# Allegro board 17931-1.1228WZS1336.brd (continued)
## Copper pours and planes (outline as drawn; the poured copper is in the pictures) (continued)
3D3V_S5 on TOP: 18.16,67.29 17.94,67.51 17.94,69.34 17.35,69.93 17.35,70.59 17.53,70.77 17.94,70.77 18.88,69.83 18.88,69.04 19.03,68.89 19.97,68.89 20.07,68.78 20.07,67.44 19.92,67.29 ; 3 cut-outs
3D3V_S5 on BOTTOM: 93.78,34.57 93.73,34.62 93.73,38.41 94.19,38.86 99.62,38.86 100.08,38.41 100.08,36.63 99.6,36.15 98.76,36.15 98.63,36.27 98.63,36.83 99.27,37.47 99.27,37.72 99.09,37.9 97.03,37.9 96.83,37.69 96.83,34.67 96.73,34.57 ; 1 cut-out
3D3V_S5 on BOTTOM: 165.74,78.28 165.48,78.54 165.48,78.79 165.36,78.92 164.85,78.92 164.72,79.05 164.72,79.71 164.54,79.88 164.54,81 164.47,81.08 164.47,81.84 164.72,82.09 164.72,83.36 164.98,83.62 164.98,84.25 165.1,84.38 165.61,84.38 165.74,84.25 165.74,81.08 165.48,80.82 165.48,80.06 166.12,79.43 166.12,78.41 165.99,78.28 ; 5 cut-outs
3D3V_S5 on BOTTOM: 74.35,36.22 74.22,36.35 74.22,38.56 74.3,38.63 75.9,38.63 76.03,38.51 76.03,36.4 75.85,36.22 ; 4 cut-outs
3D3V_S5 on BOTTOM: 52.01,124.96 50.55,126.42 49.84,126.42 48.01,128.25 48.01,131.34 47.76,131.6 47.76,131.85 47.35,132.26 47.35,133.73 47.58,133.96 50.78,133.96 51.03,133.71 51.03,130.51 51.31,130.23 52.33,130.23 52.34,130.24 52.35,130.23 53.04,130.23 53.55,130.74 57.41,130.74 57.71,130.43 57.71,128.7 57.58,128.58 56.9,128.58 56.77,128.45 56.77,125.34 56.39,124.96 ; 4 cut-outs
3D3V_S5 on BOTTOM: outline of 82 points within 32.5,40.64 152.28,94.29 ; 2 cut-outs
3D3V_S5 on BOTTOM: 208.84,49.4 208.66,49.58 208.66,51.03 208.79,51.16 210.19,51.16 210.39,50.95 210.39,49.53 210.26,49.4
3D3V_S5 on L3: 56.02,107.23 60.4,102.85 60.4,93.45 58.68,91.72 55.78,91.72 55.11,92.39 55.11,95.08 54.25,95.94 54.25,101.35 49.23,106.38 49.23,112.09 48.35,112.97 48.35,114.67 44.86,118.16 42.37,118.16 41.28,117.07 40.26,117.07 40.06,117.27 40.06,117.96 41.41,119.31 41.41,125.07 42.21,125.87 42.21,129.71 39.22,132.69 35.46,132.69 34.78,133.38 34.78,134.19 34.88,134.29 35.44,134.29 35.74,133.99 50.55,133.99 51.03,133.5 51.03,126.06 50.47,125.5 50.47,120.45 52.43,118.49 52.43,117.96 53.47,116.92 54.51,116.92 56.02,115.41
3D3V_S5 on L3: 199.27,61.52 199.27,59.31 199.6,58.98 205.97,58.98 208.16,56.8 208.16,54.76 208.36,54.56 208.36,53.72 207.47,52.83 207.42,52.83 207.06,52.48 207.06,50.75 208.16,49.66 209.4,49.66 209.55,49.81 209.93,49.81 210.98,50.85 214,50.85 215.9,48.95 215.9,47.4 216.67,46.64 217.99,46.64 218.32,46.97 218.32,52.5 214,56.82 212.73,56.82 212.33,57.21 212.33,58.99 209.78,61.55 208.23,61.55 207.67,62.1 199.85,62.1
3D3V_S5 on L6: 74.81,38.91 76.33,38.91 78.36,36.88 78.39,36.88 79.05,36.22 91.82,36.22 93.68,38.08 96.27,38.08 96.29,38.05 99.7,38.05 99.98,37.77 99.98,36.83 100.76,36.04 101.48,36.04 101.62,35.9 101.62,34.99 100.28,33.66 78.79,33.66 74.55,37.9 74.55,38.66
3D3V_S5_PCH on BOTTOM: 122.46,95.15 122.41,95.2 122.41,97.44 123.04,97.44 123.88,96.6 123.88,96.04 122.99,95.15
3D3V_S5_PCH on BOTTOM: 126.54,105.26 126.5,105.3 126.5,107.37 126.62,107.49 127.13,107.49 127.43,107.19 127.92,107.19 128.03,107.3 128.46,107.3 128.53,107.24 128.53,106.83 128,106.3 128,105.87 128.2,105.67 128.2,105.41 128.04,105.26
3D3V_S5_PCH_R on BOTTOM: 128.35,98.93 128.2,99.09 128.2,101.25 128.3,101.35 129.57,101.35 129.75,101.17 129.75,100.43 129.87,100.31 130.61,100.31 130.69,100.23 130.69,99.98 130.61,99.9 130.33,99.9 130.23,100 129.62,100 129.42,99.8 129.09,99.8 128.93,99.65 128.93,99.06 128.81,98.93
3D3V_SSD on TOP: 19.79,21.29 19.74,21.34 19.74,21.49 19.43,21.79 18.6,21.79 18.44,21.95 18.44,22.86 18.55,22.96 18.75,22.96 19.94,24.16 20.2,24.16 20.27,24.08 20.27,21.39 20.17,21.29 ; 3 cut-outs
3D3V_SSD on BOTTOM: 18.47,22.43 18.01,22.89 18.01,25.81 18.15,25.95 18.66,25.95 22.1,29.39 24.91,29.39 25.83,30.32 34.56,30.32 34.58,30.34 38.44,30.34 38.62,30.51 41.63,30.51 41.84,30.31 41.84,27.89 41.76,27.81 41.24,27.81 40.71,28.35 38.64,28.35 38.36,28.06 36.65,28.06 36.45,27.87 36.45,25.91 36.35,25.81 36.35,24.46 35.54,24.46 35.54,25.88 35.46,25.96 33.91,25.96 33.86,25.91 33.86,24.46 32.03,24.46 32.03,26.21 30.53,27.71 23.45,27.71 21.71,25.97 21.71,23.15 20.98,22.43 ; 6 cut-outs
3D3V_VCCDSW on TOP: 139.56,70.59 139.41,70.74 139.41,71.17 141.42,73.18 144.5,73.18 144.78,72.9 144.78,71.5 144.68,71.4 143.36,71.4 143.31,71.35 143.31,71.1 142.8,70.59 ; 4 cut-outs
3D3V_VCCDSW on BOTTOM: 155.1,96.7 155.1,97.82 155.6,98.32 155.98,98.32 156.06,98.25 156.06,97.74 155.83,97.51 155.83,96.7
3D3V_VCCPRIM on TOP: 107.78,91.98 107.64,91.85 107.11,91.85 107.04,91.92 107.04,92.41 106.94,92.51 104.14,92.51 104.09,92.46 103.66,92.46 103.42,92.7 101.19,92.7 101.07,92.81 101.07,93.23 101.22,93.38 101.31,93.38 101.7,93.77 101.7,94.11 101.83,94.24 104.37,94.24 104.98,93.63 105.46,93.63 105.67,93.83 107.52,93.83 107.78,93.57 ; 4 cut-outs
3D3V_VCCPRIM on TOP: 111.64,88.29 111.42,88.51 111.42,89.14 111.55,89.28 113.64,89.28 113.95,89.59 114.96,89.59 115.01,89.54 115.01,88.88 114.91,88.77 114.71,88.77 114.23,88.29 ; 1 cut-out
3D3V_VCCPRIM on BOTTOM: 106.2,92.51 106.02,92.69 106.02,93.73 106.05,93.75 107.8,93.75 108.13,93.42 108.13,92.66 107.98,92.51
3D3V_VCCPRIM on BOTTOM: 122.38,89 122.02,89.36 122.02,89.69 122.2,89.87 126.62,89.87 126.75,89.74 126.75,89.16 126.6,89
3D3V_VCCPRIM on L3: 102.37,93.47 105.39,93.47 105.64,93.72 105.64,96.72 105.8,96.88 106.03,96.88 106.23,96.68 106.23,94.72 106.41,94.53 112.37,94.53 113.62,93.29 113.62,91.97 113.92,91.67 114.73,91.67 114.79,91.62 115.95,91.62 116.84,92.51 122.43,92.51 122.81,92.13 122.81,89.69 122.46,89.33 122.13,89.33 122.05,89.41 122.05,90.1 121.85,90.3 121.49,90.3 121.16,89.97 115.94,89.97 114.56,88.58 113.99,88.58 112.09,90.48 111.89,90.48 110.38,91.98 106.35,91.98 106.23,92.1 106.23,92.4 105.99,92.64 101.3,92.64 101.04,92.9 101.04,93.44 101.2,93.6 101.6,93.6 101.7,93.7 101.7,94.08 101.86,94.24 102.11,94.24 102.29,94.06 102.29,93.55
3D3V_VCCPRTC on TOP: 164.6,66.78 164.49,66.88 164.49,67.21 165.2,67.92 167.24,67.92 167.31,67.84 167.31,66.96 167.14,66.78 ; 1 cut-out
3D3V_VCCPRTC on L5: 112.83,94.62 114.94,94.62 115.22,94.9 117.1,94.9 117.73,94.26 117.73,93.45 117.4,93.12 116.87,93.12 116.79,93.19 116.79,93.96 116.59,94.16 116.36,94.16 116.09,93.89 116.09,93.59 115.52,93.02 112.86,93.02 112.4,93.47 112.4,94.18
3D3V_WLAN on TOP: 29.52,101.35 29.24,101.63 29.24,101.68 28.96,101.96 28.96,103.51 29.24,103.79 29.24,104.9 29.52,105.18 32.16,105.18 32.21,105.13 32.21,101.68 31.88,101.35 ; 4 cut-outs
3D3V_WLAN on TOP: 56.98,93.55 56.47,94.06 56.47,98.5 55.17,99.8 55.17,103.4 53.93,104.65 52.28,104.65 51.84,105.08 49.28,105.08 48.77,104.57 45.47,104.57 45.34,104.7 45.34,104.83 45.22,104.95 43.18,104.95 43.06,105.08 43.06,105.46 42.75,105.77 42.75,106.27 42.88,106.4 43.34,106.4 44.02,105.72 44.5,105.72 44.94,106.15 44.94,106.78 45.8,107.65 47.53,107.65 47.78,107.39 49.46,107.39 49.61,107.24 50.7,107.24 50.98,107.52 54.36,107.52 60.4,101.47 60.4,95.07 58.88,93.55 ; 3 cut-outs
3D3V_WLAN on BOTTOM: 57.18,93.65 57.05,93.78 57.05,95.84 57.28,96.06 58.17,96.06 58.3,95.94 58.3,95.05 58.42,94.92 58.55,94.92 58.8,94.67 58.8,94.29 58.17,93.65
3D3V_WLAN on BOTTOM: 31.02,101.96 29.31,103.66 29.31,109.78 29.82,110.29 38.05,110.29 39.12,111.35 42.14,111.35 43.21,110.29 47.65,110.29 47.93,110.01 47.93,109.73 47.91,109.7 47.91,108.87 48.49,108.28 48.87,108.28 49.79,107.37 49.79,104.52 49.58,104.32 48.64,104.32 48.52,104.45 48.52,105.92 48.44,106 47.63,106 47.5,106.12 47.5,106.55 47.3,106.76 46.84,106.76 46.37,106.83 46.04,106.48 41.91,106.48 41.56,106.12 35.44,106.12 35.08,106.48 32.52,106.48 31.85,105.82 31.85,102.11 31.7,101.96
+DC_IN on TOP: 24.62,123.45 24.36,123.7 24.36,130.02 24.44,130.1 26.04,130.1 26.17,130.23 26.93,130.23 28.07,131.37 29.59,131.37 29.85,131.12 29.85,129.72 29.47,129.34 28.71,129.34 28.58,129.21 28.58,128.96 28.51,128.89 26.41,128.89 26.29,128.78 26.29,127.79 26.17,127.66 25.76,127.66 25.66,127.56 25.66,126.57 25.94,126.29 26.55,126.29 26.72,126.11 26.72,125.48 26.2,124.96 26.2,124.63 25.96,124.39 25.96,123.8 25.61,123.45 ; 7 cut-outs
+DC_IN_C on TOP: 20.78,120.45 20.58,120.65 20.58,124.92 20.37,125.12 17.58,125.12 17.35,125.35 17.35,127.38 17.4,127.43 18.42,127.43 19.41,126.44 20.67,126.44 20.77,126.54 20.77,129.38 20.75,129.39 20.75,129.87 20.98,130.1 23.83,130.1 24.21,129.72 24.21,120.65 24.01,120.45 ; 4 cut-outs
+DC_IN_C on BOTTOM: 21.96,124.14 21.8,124.31 21.8,128.04 22.02,128.27 24.16,128.27 24.95,127.48 24.95,124.68 24.41,124.14
+SDC_IN on TOP: 34.93,123.5 34.8,123.62 34.8,124.13 34.55,124.39 33.15,124.39 33.02,124.51 33.02,125.02 32.9,125.15 31.91,125.15 31.8,125.25 31.8,125.63 31.63,125.81 31.19,125.81 30.86,125.48 30.86,124 30.74,123.88 30.1,123.88 29.98,124 29.98,126.85 30.43,127.31 31.04,127.31 31.22,127.13 31.22,126.65 31.58,126.29 32.62,126.29 33.15,126.82 33.48,126.82 33.63,126.98 33.63,127.53 33.18,127.99 33.18,128.6 33.28,128.7 35.26,128.7 35.39,128.58 35.39,127.48 35.44,127.43 35.44,125.78 35.82,125.4 35.82,123.75 35.56,123.5 ; 8 cut-outs
+SDC_IN on TOP: 203.03,52.55 202.82,52.76 202.82,53.75 203.89,54.81 204.3,54.81 204.37,54.74 204.37,53.52 204.27,53.42 203.86,53.42 203.63,53.19 203.63,52.63 203.56,52.55 ; 1 cut-out
+SDC_IN on TOP: 30.94,108.46 30.79,108.61 30.79,110.47 30.84,110.52 31.35,110.52 31.4,110.47 31.4,109.83 31.75,109.48 31.75,108.48 31.73,108.46 ; 1 cut-out
+SDC_IN on BOTTOM: 174.5,51.18 173.82,51.87 173.82,52.66 172.88,53.6 142.45,53.6 141.71,54.33 133.07,54.33 132.39,53.65 127.19,53.65 126.29,52.74 104.21,52.74 102.62,54.33 90.31,54.33 88.25,56.4 41.79,56.4 40.71,57.48 40.71,59.93 40.69,59.95 40.69,62.13 41.71,63.15 43.11,63.15 43.44,62.82 84.97,62.82 89.97,67.82 104.35,67.82 110.8,61.37 129.8,61.37 130.53,62.1 152.15,62.1 154.1,64.06 171.2,64.06 171.83,63.43 171.83,57.84 172.85,56.82 176.15,56.82 176.91,57.58 178.31,57.58 178.32,57.6 178.34,57.58 183.47,57.58 183.85,57.2 183.85,55.45 182.08,53.68 177.87,53.68 177.65,53.47 177.65,52.17 176.66,51.18
+SDC_IN on L3: 48.87,61.72 48.87,78.89 50.73,80.75 50.73,91.34 50.5,91.57 50.49,91.57 47.69,94.36 47.69,96.33 41.02,103 41.02,114.76 40.36,115.42 40.36,116.08 39.83,116.61 39.83,118.01 40.01,118.19 40.01,119.81 41.02,120.83 41.02,123.22 39.37,124.87 37.72,124.87 35.84,126.75 32.36,126.75 29.75,124.13 29.75,118.72 29.81,118.66 29.81,105.67 32.13,103.34 32.13,102.57 36.4,98.3 37.47,98.3 38.51,97.26 38.51,95.81 41.1,93.22 42.56,93.22 42.77,93 42.77,92.38 42.36,91.96 42.36,73.99 40.24,71.88 40.24,66.02 40.2,65.98 40.2,62.02 40.62,61.6 41.53,61.6 42.22,60.9 48.06,60.9
+SDC_IN_SW on TOP: 35.69,126.16 35.56,126.29 35.56,127.69 35.52,127.73 35.52,128.51 35.72,128.7 36.86,128.7 37.04,128.53 37.04,128.04 36.96,127.97 36.96,126.29 36.83,126.16 ; 2 cut-outs
+V_VREF_PATH1 on TOP: 73.03,38.91 72.82,39.12 72.82,40.23 72.93,40.34 73.38,40.34 73.46,40.26 73.46,39.45 73.54,39.37 74.09,39.37 74.17,39.3 74.17,38.96 74.12,38.91 73.28,38.91 73.28,38.96 73.23,38.91
AUD_AGND on TOP: 18.67,16.61 18.47,16.82 18.47,18.95 19.76,20.25 21.09,20.25 21.21,20.12 21.21,19.2 20.83,18.82 20.27,18.82 20.12,18.67 19.51,18.67 19.13,18.29 19.13,16.74 19,16.61 ; 1 cut-out
AUD_AGND on TOP: 21.67,9.17 21.62,9.22 21.62,9.91 21.49,10.03 21.09,10.03 20.96,10.16 20.96,10.54 21.03,10.62 22.02,10.62 22.23,10.82 22.81,10.82 22.84,10.8 22.84,10.19 22.28,9.63 22.28,9.25 22.2,9.17 ; 1 cut-out
AUD_AGND on L2GND: 22.56,4.43 22.29,4.7 22.29,6.61 21.67,7.23 14.18,7.23 13.16,8.24 1.41,8.24 1.47,8.39 1.6,8.47 2.3,8.91 2.57,9.7 2.57,10.61 12.71,10.61 13.91,11.47 13.47,12.88 13.47,17.39 13.91,18.8 12.71,19.66 2.57,19.66 2.57,21.27 2.63,21.43 2.77,21.51 3.11,21.62 3.41,21.83 17.96,21.83 19.48,20.31 20.88,20.31 21.13,20.05 22.05,20.05 22.55,20.55 22.55,21.04 22.57,21.07 23.04,21.07 23.18,20.93 23.18,17.37 24.83,15.72 24.83,12.04 25.2,11.67 27.23,11.67 27.24,11.66 27.24,10.64 28.26,9.63 28.26,8.61 28.39,8.48 28.39,6.32 29.13,5.58 32.59,5.58 33.59,6.58 33.59,8.89 32.34,10.15 31.71,10.15 30.82,11.04 29.67,11.04 29.02,11.69 29.02,12.93 29.04,12.94 29.9,12.94 30.79,12.05 31.29,12.05 31.93,11.42 32.85,11.42 33.61,12.18 34.47,12.18 34.48,12.17 34.48,10.26 34.61,10.13 34.61,5.59 33.83,4.81 23.93,4.81 23.55,4.43
AUD_AGND on L4VCC: 22.56,4.43 22.29,4.7 22.29,6.61 21.67,7.23 14.18,7.23 13.16,8.24 1.41,8.24 1.47,8.39 1.6,8.47 2.3,8.91 2.57,9.7 2.57,10.61 12.71,10.61 13.91,11.47 13.47,12.88 13.47,17.39 13.91,18.8 12.71,19.66 2.57,19.66 2.57,21.27 2.63,21.43 2.77,21.51 3.11,21.62 3.41,21.83 17.96,21.83 19.48,20.31 20.88,20.31 21.13,20.05 22.05,20.05 22.55,20.55 22.55,21.06 22.56,21.07 23.04,21.07 23.18,20.93 23.18,17.37 24.83,15.72 24.83,12.04 25.2,11.67 27.23,11.67 27.24,11.66 27.24,10.64 28.26,9.63 28.26,8.61 28.39,8.48 28.39,6.32 29.13,5.58 32.59,5.58 33.59,6.58 33.59,8.89 32.34,10.15 31.71,10.15 30.82,11.04 29.67,11.04 29.02,11.69 29.02,12.93 29.04,12.94 29.9,12.94 30.79,12.05 31.29,12.05 31.93,11.42 32.85,11.42 33.61,12.18 34.47,12.18 34.48,12.17 34.48,10.26 34.61,10.13 34.61,5.59 33.83,4.81 23.93,4.81 23.55,4.43
AUD_AGND on L5: 2.3,8.92 2.57,9.7 2.57,10.61 12.71,10.61 13.91,11.47 13.47,12.88 13.47,17.39 13.91,18.8 12.71,19.66 2.57,19.66 2.57,21.27 2.63,21.43 2.77,21.51 3.07,21.6 3.33,21.77 18.04,21.77 19.56,20.25 20.83,20.25 21.09,19.99 22.1,19.99 22.48,20.37 22.48,21.01 22.61,21.13 22.74,21.13 23.37,20.5 23.37,17.45 24.77,16.05 24.77,11.99 25.15,11.61 27.05,11.61 27.18,11.48 27.18,10.59 28.2,9.58 28.2,8.56 28.32,8.43 28.32,6.4 29.21,5.51 32.77,5.51 33.66,6.4 33.66,8.92 32.36,10.21 31.75,10.21 30.86,11.1 29.59,11.1 29.09,11.61 29.09,12.8 29.2,12.92 29.81,12.92 30.74,11.99 31.19,11.99 31.83,11.36 32.9,11.36 33.66,12.12 34.29,12.12 34.42,11.99 34.42,10.21 34.55,10.09 34.55,5.64 33.79,4.88 23.88,4.88 23.5,4.5 22.61,4.5 22.36,4.75 22.36,5.77 22.34,5.78 22.34,6.77 21.82,7.29 14.23,7.29 13.21,8.31 1.55,8.31 1.53,8.33 1.53,8.43 1.55,8.45 1.6,8.47
AUD_AGND on L7GND: 14.18,7.23 13.16,8.24 1.41,8.24 1.47,8.39 1.6,8.47 2.3,8.91 2.57,9.7 2.57,10.61 12.71,10.61 13.91,11.47 13.47,12.88 13.47,17.39 13.91,18.8 12.71,19.66 2.57,19.66 2.57,21.27 2.63,21.43 2.77,21.51 3.11,21.62 3.41,21.83 17.96,21.83 19.48,20.31 20.88,20.31 21.13,20.05 22.05,20.05 22.55,20.55 22.55,21.06 22.56,21.07 23.04,21.07 23.18,20.93 23.18,17.37 24.83,15.72 24.83,13.97 24.69,13.83 22.66,13.83 21.53,12.7 21.53,10.8 21.13,10.4 20.24,10.4 17.07,7.23
AUD_RING on TOP: 16.39,10.52 16.34,10.57 16.34,12.75 16.49,12.9 17.16,12.9 17.26,12.8 17.26,10.55 17.22,10.52 ; 2 cut-outs
AUD_RING on TOP: 23.65,14.63 22.56,15.72 22.56,16.36 22.13,16.79 21.36,16.79 21.31,16.84 21.31,17.27 21.36,17.32 22.25,17.32 23.63,15.95 23.63,15.27 24.01,14.89 24.82,14.89 24.84,14.86 24.84,14.66 24.82,14.63
AUD_RING on L3: 22.94,16.33 23.65,16.33 24.17,15.81 24.17,14.34 24.06,14.23 22.69,14.23 22.69,16.08
AUD_SLEEVE on TOP: 23.12,14.23 22.15,15.19 21.97,15.19 21.34,15.83 21.34,16.49 21.4,16.55 22.09,16.55 22.41,16.23 22.41,15.7 23.6,14.5 24.79,14.5 24.84,14.45 24.84,14.25 24.82,14.23
AUD_SLEEVE on TOP: 17.83,16.03 17.71,16.16 16.39,16.16 16.28,16.26 16.28,16.92 16.39,17.02 17.45,17.02 17.68,17.25 17.68,17.78 17.78,17.88 18.14,17.88 18.27,17.76 18.27,16.74 18.49,16.51 18.49,16.26 18.27,16.03
AUD_SPK_L+ on TOP: 17.25,3.56 17.12,3.68 17.12,4.5 17.22,4.6 17.83,4.6 18.06,4.37 20.17,4.37 20.25,4.29 20.25,3.68 20.12,3.56
AUD_SPK_L+ on TOP: 30.89,12.45 29.9,13.44 29.04,13.44 29.01,13.46 29.01,13.67 29.04,13.69 30,13.69 30.36,13.34 31.58,13.34 31.8,13.11 31.8,12.68 31.58,12.45
AUD_SPK_L+ on BOTTOM: 29.82,11.79 29.59,12.02 29.59,12.73 29.84,12.97 30.98,12.97 31.17,13.16 31.7,13.16 31.85,13.01 31.85,12.12 31.52,11.79
AUD_SPK_L+_C on TOP: 14.94,3.91 14.86,3.99 14.86,4.88 14.91,4.93 16.82,4.93 16.94,4.8 16.94,4.07 16.79,3.91
AUD_SPK_L+_C on BOTTOM: 8.92,3.86 8.64,4.14 8.64,6.28 8.82,6.45 9.58,6.45 9.66,6.38 9.66,4.04 9.48,3.86
AUD_SPK_L- on TOP: 30.46,13.41 30.05,13.82 29.06,13.82 29.01,13.87 29.01,14.05 29.04,14.07 30.81,14.07 30.94,13.95 30.94,13.56 30.79,13.41
AUD_SPK_L- on TOP: 17.3,5.06 17.15,5.21 17.15,5.79 17.25,5.89 19.79,5.89 19.92,5.77 19.92,5.16 19.82,5.06
AUD_SPK_L-_C on TOP: 14.91,5.21 14.86,5.26 14.86,6.15 14.94,6.22 16.67,6.22 16.94,5.94 16.94,5.31 16.84,5.21
AUD_SPK_L-_C on BOTTOM: 7.47,3.86 7.14,4.19 7.14,6.33 7.27,6.45 8.51,6.45 8.51,4.01 8.36,3.86
AUD_SPK_R+ on TOP: 17.25,1.35 17.12,1.47 17.12,2.21 17.22,2.31 17.91,2.31 18.04,2.19 18.06,2.19 18.19,2.06 20.12,2.06 20.3,1.88 20.3,1.45 20.2,1.35
AUD_SPK_R+ on TOP: 29.04,14.63 29.01,14.66 29.01,14.86 29.04,14.89 29.75,14.89 30.23,15.37 30.61,15.37 30.74,15.24 30.74,14.81 30.56,14.63
AUD_SPK_R+ on BOTTOM: 30.2,14.53 30,14.73 30,15.8 30.41,16.21 32.18,16.21 32.36,16.03 32.36,15.17 32.29,15.09 31.04,15.09 30.48,14.53
AUD_SPK_R+_C on TOP: 14.94,1.37 14.86,1.45 14.86,2.34 14.91,2.39 16.72,2.39 16.82,2.29 16.82,1.47 16.72,1.37
AUD_SPK_R+_C on BOTTOM: 11,2.74 10.87,2.87 10.87,6.43 10.9,6.45 11.76,6.45 11.84,6.38 11.84,3.1 11.48,2.74
AUD_SPK_R- on TOP: 31.17,14.02 30.97,14.23 29.06,14.23 29.01,14.28 29.01,14.45 29.09,14.53 30.58,14.53 30.81,14.76 31.83,14.76 31.93,14.66 31.93,14.15 31.8,14.02
AUD_SPK_R- on TOP: 17.22,2.59 17.07,2.74 17.07,3.4 17.12,3.46 20.53,3.46 20.58,3.51 20.58,3.89 20.65,3.96 21.11,3.96 21.16,3.91 21.16,2.87 21.03,2.74 19.89,2.74 19.84,2.8 18.37,2.8 18.32,2.74 18.06,2.74 17.91,2.59
AUD_SPK_R- on BOTTOM: 32.31,13.64 32.11,13.84 31.6,13.84 31.14,14.3 31.14,14.78 31.28,14.92 32.85,14.92 33.28,14.49 33.28,13.87 33.05,13.64
AUD_SPK_R-_C on TOP: 14.94,2.64 14.86,2.72 14.86,3.61 14.91,3.66 16.84,3.66 16.94,3.56 16.94,2.77 16.82,2.64
AUD_SPK_R-_C on BOTTOM: 9.91,4.01 9.78,4.14 9.78,6.38 9.86,6.45 10.62,6.45 10.73,6.34 10.73,4.08 10.67,4.01
BT+ on BOTTOM: 150.02,31.17 150,31.18 145.02,31.18 142.37,33.83 142.37,41.07 142.45,41.15 144.35,41.15 144.43,41.07 144.43,40.46 144.55,40.34 145.52,40.34 146.13,39.73 151.56,39.73 152.96,38.33 152.96,35.28 153.14,35.1 154.33,35.1 154.87,34.57 154.87,33.55 155.02,33.4 170.36,33.4 170.49,33.28 173.33,33.28 173.36,33.3 173.36,33.55 173.71,33.55 173.92,33.76 181.26,33.76 181.28,33.73 181.28,32.54 181.16,32.41 178.18,32.41 177.9,32.13 177.9,31.29 177.78,31.17 ; 3 cut-outs
BT+ on L3: 151.39,34.22 152.53,34.22 152.78,33.96 152.78,33.71 153.04,33.45 173.49,33.45 173.79,33.15 173.79,31.4 173.69,31.29 151.51,31.29 151.13,31.68 151.13,33.96
DCBATOUT on TOP: 154.69,81.66 154.18,82.17 154.18,88.83 154.28,88.93 155.17,88.93 155.43,88.67 157.41,88.67 157.61,88.47 157.61,82.5 157.48,82.37 156.92,82.37 156.21,81.66 ; 6 cut-outs
DCBATOUT on TOP: 138.64,81.89 138.1,82.42 138.1,87.53 138.31,87.73 138.79,87.73 138.86,87.66 140.01,87.66 140.11,87.76 140.11,88.72 140.47,89.08 141.13,89.08 141.3,88.9 141.3,83.57 141.53,83.34 141.53,82.48 141.43,82.37 141.05,82.37 140.57,81.89 ; 2 cut-outs
DCBATOUT on TOP: 174.91,61.42 174.53,61.8 174.53,64.75 175.42,65.63 175.59,65.63 178.64,62.59 178.64,62.51 178.39,62.26 177.73,62.26 176.89,61.42 ; 5 cut-outs
DCBATOUT on TOP: 111.92,143.64 111.71,143.84 111.71,144.27 111.41,144.58 107.98,144.58 107.85,144.71 107.85,146 107.95,146.1 112.27,146.1 113.03,145.34 113.03,144.15 112.53,143.64 ; 2 cut-outs
DCBATOUT on TOP: 108.59,137.26 108.13,137.72 105.72,137.72 105.64,137.8 105.64,139.73 105.72,139.8 109.45,139.8 110.72,138.53 110.72,137.62 110.37,137.26 ; 1 cut-out
DCBATOUT on TOP: 119.74,34.27 119.56,34.44 119.56,36.35 120.83,37.62 123.8,37.62 124.29,38.1 126.39,38.1 126.98,37.52 126.98,35 126.71,34.74 126.33,34.74 125.86,34.27 ; 4 cut-outs
DCBATOUT on TOP: 94.62,140.77 94.49,140.9 94.49,143.44 94.62,143.56 96.02,143.56 96.14,143.69 96.57,143.69 96.7,143.56 96.7,141.45 96.02,140.77 ; 3 cut-outs
DCBATOUT on TOP: 76.46,32.59 76.41,32.64 76.41,33.96 76.58,34.14 79.51,34.14 79.73,33.91 79.73,33.35 78.97,32.59 ; 3 cut-outs
DCBATOUT on TOP: 63.25,137.21 62.87,137.59 62.87,139.63 63,139.75 65.15,139.75 65.28,139.63 65.28,138.61 63.88,137.21 ; 2 cut-outs
DCBATOUT on BOTTOM: 94.49,138.81 94.48,138.82 94.48,143.6 94.67,143.79 97.18,143.79 97.59,143.38 97.59,140.74 96.57,139.73 96.57,139.04 96.35,138.81 ; 6 cut-outs
DCBATOUT on BOTTOM: 53.55,132.28 53.53,132.3 52.95,132.3 52.78,132.46 52.78,133 53.95,134.16 54.49,134.16 55.76,135.43 55.76,139.32 56.21,139.78 59.46,139.78 60.32,140.63 60.32,141.56 60.59,141.83 61.29,141.83 62.43,141.31 63.66,141.07 63.83,141.07 64.04,140.87 64.04,139.14 64.39,138.79 64.39,137.29 64.32,137.21 62.89,137.21 62.18,137.92 62.18,139.17 61.95,139.4 61.67,139.4 60.33,138.05 59.08,138.05 58.68,137.64 57.84,137.64 57.66,137.47 57.66,136.73 57.53,136.6 57.53,134.42 57.79,134.16 58.3,134.16 58.68,133.78 58.68,132.61 58.58,132.51 57.53,132.51 57.31,132.28 ; 5 cut-outs
DCBATOUT on BOTTOM: 208.69,38.91 208.54,39.07 208.54,40.26 209.3,41.02 209.3,42.93 209.32,42.95 211.43,42.95 211.84,42.55 211.84,41.56 211.66,41.38 211.23,41.38 211.03,41.17 211.03,40.77 211.23,40.57 211.61,40.57 211.84,40.34 211.84,39.52 211.23,38.91 ; 1 cut-out
DCBATOUT on BOTTOM: 181.71,32.41 181.59,32.54 181.59,33.86 181.41,34.04 178.74,34.04 178.51,34.27 178.51,35.1 178.16,35.46 178.16,36.37 178.26,36.48 179.05,36.48 179.12,36.55 179.12,37.42 180.8,37.42 181.61,36.6 183.29,36.6 183.29,39.55 183.26,39.57 183.04,39.57 183.01,39.6 183.01,39.85 182.86,40.01 182.53,40.01 181.84,40.69 181.69,40.69 181.69,43.11 181.71,43.13 185.04,43.13 185.04,39.32 185.25,39.12 185.25,36.83 185.04,36.63 185.04,36.15 184.76,35.87 184.15,35.87 183.95,35.66 183.95,32.64 183.72,32.41 ; 7 cut-outs
DCBATOUT on BOTTOM: 74.02,139.6 73.89,139.73 73.89,140.31 73.71,140.49 72.06,140.49 71.99,140.56 71.99,143.56 72.14,143.71 73.28,143.71 73.89,143.1 73.89,142.9 74.15,142.65 75.64,142.65 75.8,142.5 75.8,140.01 75.39,139.6 ; 2 cut-outs
DCBATOUT on BOTTOM: 183.57,57.71 183.52,57.76 179.91,57.76 179.73,57.94 179.73,59.84 179.56,60.02 178.34,60.02 177.73,59.41 176.1,59.41 175.66,59.86 175.66,61.38 175.59,61.44 174.73,61.44 174.55,61.62 174.55,65.03 175.64,66.12 179.43,66.12 179.58,66.27 179.58,66.65 179.35,66.88 179.35,67.74 179.4,67.79 180.85,67.79 180.93,67.72 180.93,64.97 180.8,64.85 179.35,64.85 179.02,64.52 179.02,63.45 179.12,63.35 179.96,63.35 182.78,60.53 183.11,60.53 183.34,60.76 184.81,60.76 184.81,57.71 ; 2 cut-outs
DCBATOUT on BOTTOM: 138.1,81.92 134.95,85.07 134.95,88.32 137.87,88.32 138.64,89.08 141,89.08 141.18,88.9 141.18,82.44 140.66,81.92 ; 2 cut-outs
DCBATOUT on BOTTOM: 44.02,29.69 42.9,30.81 41.76,30.81 41.3,31.27 38.99,31.27 38.66,31.6 38.66,33.86 38.69,33.88 39.73,33.88 40.14,34.29 40.14,34.98 40.52,35.36 41.66,35.36 41.79,35.23 41.79,34.22 41.93,34.07 43.94,34.07 43.94,34.06 55.4,34.06 56.77,32.69 60.76,32.69 61.34,33.28 76.1,33.28 76.33,33.5 76.33,34.6 76.58,34.85 79.66,34.85 80.5,34.01 80.5,30.38 79.81,29.69 ; 7 cut-outs
DCBATOUT on BOTTOM: 155.5,78.33 155.43,78.41 155.43,79.12 154.18,80.37 154.18,83.31 154.05,83.44 154.05,88.72 154.28,88.95 155.15,88.95 155.27,88.83 155.27,87.68 155.4,87.56 157.61,87.56 157.89,87.28 157.89,85.17 157.99,85.07 157.99,82.75 157.67,82.44 157.67,82.18 156.9,81.41 156.9,78.89 156.34,78.33 ; 8 cut-outs
DCBATOUT on L3: outline of 169 points within 62.11,32.28 211.65,145.85 ; 8 cut-outs
DCBATOUT_LCD on TOP: 218.09,37.09 217.22,37.95 215.17,37.95 215.01,38.1 215.01,38.46 215.06,38.51 219.74,38.51 219.97,38.28 219.97,37.8 219.26,37.09
DCBATOUT_LCD on BOTTOM: 216.79,37.09 216.59,37.29 216.59,38.3 216.44,38.46 214.53,38.46 214.1,38.89 213.03,38.89 212.93,38.99 212.93,42.88 213.01,42.95 214.86,42.95 215.06,42.75 215.06,41.33 218.19,38.2 219.33,38.2 219.64,38.51 219.94,38.51 220.04,38.41 220.04,37.21 219.92,37.09
GPU_I2C on BOTTOM: 140.08,104.83 139.65,105.26 139.65,106.5 139.7,106.55 142.34,106.55 142.5,106.4 142.5,105.13 142.19,104.83 ; 3 cut-outs
JGND on TOP: 15.83,125.86 15.78,125.91 15.78,127.84 16.64,128.7 20.48,128.7 20.55,128.63 20.55,126.62 19.43,126.62 18.42,127.64 17,127.64 16.84,127.48 16.84,125.96 16.74,125.86 ; 2 cut-outs
JGND on BOTTOM: 16.79,122.73 16.67,122.86 16.67,124.36 17,124.69 17,128.3 17.78,129.08 19.46,129.08 19.99,128.55 19.99,126.44 19.56,126.01 19.56,123.9 18.39,122.73
M_VREF_CA_DIMMA on TOP: 70.87,40.57 70.36,41.07 70.36,41.96 70.49,42.09 73.03,42.09 73.41,41.71 73.41,40.82 73.16,40.57 ; 2 cut-outs
M_VREF_CA_DIMMB on TOP: 147.58,41.86 147.35,42.09 147.35,43.71 147.45,43.82 148.24,43.82 148.72,44.3 148.72,44.65 148.9,44.83 149.15,44.83 149.3,44.68 149.3,44.15 148.9,43.74 148.9,42.62 148.72,42.44 148.72,41.89 148.69,41.86 ; 2 cut-outs
MCT on BOTTOM: 26.29,82.78 24.23,84.84 24.23,85.9 24.41,86.08 27.23,86.08 27.49,85.83 27.49,82.98 27.28,82.78
PEX_PLLVDD on TOP: 131.19,148.64 130.91,148.92 130.91,150.24 131.04,150.37 132.46,150.37 132.59,150.5 132.59,151.77 132.67,151.84 133.45,151.84 133.61,151.69 133.61,149.15 133.1,148.64 ; 2 cut-outs
PEX_SVDD on TOP: 124.54,131.12 122.89,132.77 122.89,133.05 123.4,133.55 123.4,133.81 123.45,133.86 123.68,133.86 123.75,133.78 123.75,133.63 123.98,133.4 125.17,133.4 125.94,132.64 125.94,132.34 124.72,131.12 ; 2 cut-outs
PS_ID_R on TOP: 18.13,123.33 18.04,123.42 18.04,124.89 20.2,124.89 20.45,124.64 20.45,123.5 20.28,123.33 ; 1 cut-out
PWR_1D05V_PH on BOTTOM: 99.37,131.07 99.32,131.12 99.32,133.68 100.08,134.44 100.08,135.26 100.1,135.28 100.84,135.28 100.92,135.36 100.92,135.87 100.99,135.94 104.52,135.94 104.78,135.69 104.78,135.05 104.65,134.93 101.81,134.93 101.78,134.9 101.78,133.96 101.83,133.91 102.75,133.91 102.9,133.76 102.9,131.12 102.85,131.07
PWR_1D8V on TOP: 61.88,39.17 61.86,39.18 61.46,39.18 60.86,39.78 60.86,42.24 60.99,42.37 66.53,42.37 66.93,41.96 66.93,39.75 66.35,39.17
PWR_1D8V on BOTTOM: 65.43,38.25 65.36,38.33 65.36,39.93 65.03,40.26 65.03,41.71 65.23,41.91 66.78,41.91 67.16,41.53 67.16,40.23 67.74,39.65 67.74,38.33 67.67,38.25 ; 2 cut-outs
PWR_1D8V_PH on BOTTOM: 65.41,36.35 65.38,36.37 65.38,37.54 65.43,37.59 67.54,37.59 67.8,37.85 67.87,37.85 67.95,37.77 67.95,36.63 67.67,36.35
PWR_1D8V_VIN on BOTTOM: 72.57,36.2 72.44,36.32 72.44,36.83 71.81,37.47 70.16,37.47 70.08,37.54 70.08,37.85 70.16,37.92 73.97,37.92 74.07,37.82 74.07,36.37 73.89,36.2 ; 1 cut-out
PWR_1D35V_BOOT on BOTTOM: 111.56,146.94 111.51,146.99 111.51,147.37 111,147.88 111,148.9 111.23,148.9 111.48,148.64 112.19,148.64 112.4,148.44 112.4,147.07 112.27,146.94 ; 1 cut-out
PWR_1D35V_LDO_P5 on BOTTOM: 111.13,150.32 111.08,150.37 111.08,150.75 111.36,151.03 111.89,151.03 112.23,151.37 112.23,152.19 112.42,152.38 113.06,152.38 113.19,152.25 113.19,150.65 112.86,150.32 ; 1 cut-out
PWR_1D35V_PHASE on TOP: 112.65,149.53 112.4,149.79 112.4,150.04 112.65,150.29 113.67,150.29 113.8,150.17 113.8,149.61 113.72,149.53
PWR_1D35V_PHASE on BOTTOM: 108.08,148.13 107.83,148.39 107.83,148.9 108.21,149.28 109.1,149.28 109.22,149.15 109.22,148.9 108.46,148.13
PWR_1D35V_PHASE on BOTTOM: 114.3,145.59 114.05,145.85 114.05,148.41 113.64,148.82 111.59,148.82 111,149.4 111,149.66 112.65,149.66 113.24,150.24 114.86,150.24 116.21,148.9 116.21,145.85 115.95,145.59 ; 2 cut-outs
PWR_1V_VGA on TOP: 116.21,141.53 116.08,141.66 116.08,142.17 115.32,142.93 115.32,144.07 115.57,144.32 117.86,144.32 117.99,144.2 117.99,141.66 117.86,141.53
PWR_1V_VGA on BOTTOM: 113.54,140.51 113.46,140.59 113.46,141.43 113.69,141.66 114.76,141.66 115.07,141.96 115.07,144.02 115.19,144.15 117.48,144.15 117.86,143.77 117.86,140.64 117.73,140.51 ; 4 cut-outs
PWR_1V_VGA_LX on BOTTOM: 113.26,141.83 113.24,141.86 113.24,142.62 112.88,142.62 112.65,142.85 111.79,142.85 111.79,143.16 112.65,143.16 112.78,143.28 112.78,143.69 113.21,144.12 114.43,144.12 114.61,143.94 114.61,142.01 114.43,141.83
PWR_1V_VGA_VIN on BOTTOM: 106.58,141.3 106.53,141.35 106.53,142.7 106.99,143.16 110.7,143.16 110.7,142.85 110.01,142.85 108.46,141.3 ; 4 cut-outs
PWR_2D5V on TOP: 90.1,35.13 89.88,35.35 89.88,38.16 90.68,38.96 91.21,38.96 91.34,38.84 91.34,36.42 91.19,36.27 91.19,35.28 91.04,35.13 ; 3 cut-outs
PWR_2D5V on BOTTOM: 89.79,35.15 89.64,35.31 89.64,37.16 91.89,39.41 91.89,39.74 92.13,39.98 94.16,39.98 94.26,39.88 94.26,39.27 93.6,38.61 93.6,36.65 93.45,36.5 91.95,36.5 91.8,36.65 91.29,36.65 90.94,36.3 90.94,35.31 90.78,35.15 ; 1 cut-out
PWR_3D3V_LDO on BOTTOM: 60.05,130.48 59.72,130.81 59.72,132.23 59.74,132.26 60.15,132.26 60.2,132.21 60.2,132.13 60.71,131.62 61.47,131.62 61.73,131.88 61.73,132.13 61.85,132.26 62.61,132.26 62.74,132.13 62.74,130.86 62.36,130.48 ; 1 cut-out
PWR_3D3V_PH on BOTTOM: 59.19,124.64 58.42,125.4 58.42,132.01 58.7,132.28 59.03,132.28 59.13,132.18 59.13,130.4 59.69,129.85 61.34,129.85 61.73,129.47 61.73,125.05 61.32,124.64
PWR_3D3V_PH on L6: 57.87,134.77 58.23,134.77 58.41,134.59 58.41,132.78 58.24,132.61 57.78,132.61 57.54,132.86 57.54,134.44
PWR_5V_PH on BOTTOM: 42.42,34.98 41.91,35.49 41.91,35.61 42.04,35.74 43.06,35.74 43.18,35.87 43.18,39.3 43.34,39.45 46.03,39.45 46.1,39.38 46.1,35.5 45.57,34.98
PWR_5V_VCC on BOTTOM: 42.04,36.37 41.91,36.5 41.91,36.76 42.42,37.26 42.42,38.03 42.29,38.15 42.29,38.41 42.04,38.66 42.04,39.42 42.29,39.68 42.93,39.68 43.06,39.55 43.06,36.5 42.93,36.37
PWR_CHG_BGATE/HG2 on BOTTOM: 199.22,44.53 199.11,44.63 199.11,45.29 201.25,47.42 201.88,47.42 201.93,47.37 201.93,46.76 201.91,46.74 201.22,46.74 200.66,46.18 200.66,45.92 200.16,45.42 200.16,44.63 200.05,44.53
PWR_CHG_BOOT1 on BOTTOM: 202.97,50.7 202.95,50.73 202.95,51.82 202.52,52.25 202.52,52.55 202.16,52.91 202.16,53.09 202.31,53.24 202.54,53.24 203.15,52.63 203.15,50.75 203.1,50.7
PWR_CHG_BOOT2 on BOTTOM: 198.25,47.73 198.15,47.83 198.15,48.62 198.25,48.72 199.67,48.72 199.85,48.54 200.31,48.54 200.69,48.92 201.53,48.92 201.55,48.9 201.55,48.77 201.5,48.72 200.84,48.72 200.36,48.24 199.52,48.24 199.01,47.73
PWR_CHG_BT1_R on BOTTOM: 200.28,54.41 199.65,55.04 199.14,55.04 199.04,55.14 199.04,55.83 199.22,56.01 200.76,56.01 201.12,55.65 201.12,54.51 201.02,54.41 ; 1 cut-out
PWR_CHG_LGATE1 on TOP: 190.63,47.55 190.5,47.68 190.5,48.57 190.63,48.69 192.15,48.69 192.41,48.44 192.41,47.93 192.03,47.55
PWR_CHG_LGATE1 on BOTTOM: 201.76,50.62 200.94,51.44 200.71,51.44 200.46,51.69 200.46,52.05 200.61,52.2 200.97,52.2 201.68,51.49 201.86,51.49 202.01,51.33 202.01,50.7 201.93,50.62
PWR_CHG_LGATE2/ASGATE on BOTTOM: 200.79,49.94 200.49,50.24 199.52,50.24 199.44,50.17 198.91,50.17 198.78,50.29 198.78,50.6 199.22,51.03 200.05,51.03 200.92,50.17 201.55,50.17 201.58,50.14 201.58,49.96 201.55,49.94
PWR_CHG_NGATE on BOTTOM: 198.25,46.56 198.2,46.61 198.2,47.45 198.25,47.5 199.01,47.5 199.65,48.13 200.41,48.13 200.82,48.54 201.53,48.54 201.58,48.49 201.58,48.39 201.53,48.34 201.09,48.34 199.32,46.56
PWR_CHG_PHASE1 on BOTTOM: 186.69,47.55 186.19,48.06 186.19,52.25 186.69,52.76 194.95,52.76 195.46,52.25 195.46,51.87 195.13,51.54 195.13,48.64 195.05,48.57 191.54,48.57 191.27,48.29 191.27,47.68 191.14,47.55
PWR_CHG_PHASE1 on BOTTOM: 202.16,50.7 202.14,50.73 202.14,51.36 201.92,51.58 201.74,51.58 200.99,52.33 200.99,52.76 201.07,52.83 201.32,52.83 201.53,52.63 201.53,52.22 201.78,51.97 201.93,51.97 202.34,51.56 202.34,50.73 202.31,50.7
PWR_CHG_PHASE2 on BOTTOM: 174.63,40.16 174.63,44.12 174.88,44.38 174.88,47.52 176,48.64 176,50.01 177.3,51.31 178.46,51.31 179.4,52.25 183.92,52.25 185.25,50.93 185.25,44.76 184.99,44.5 184,44.5 183.9,44.4 183.9,43.51 183.75,43.36 181.56,43.36 181.33,43.13 181.33,40.69 177.8,40.69 177.68,40.57 177.68,40.16
PWR_CHG_PHASE2_R on BOTTOM: 198.86,49.53 198.43,49.1 197.67,49.1 197.59,49.18 197.59,49.94 197.69,50.04 199.9,50.04 200.05,50.19 200.36,50.19 200.79,49.76 201.55,49.76 201.6,49.71 201.6,49.58 201.55,49.53
PWR_CHG_PROCHOT#_R on BOTTOM: 206.71,44.88 206.66,44.93 206.66,45.7 206.48,45.87 206.05,45.87 205.97,45.95 205.97,46.33 206.07,46.43 207.37,46.43 207.72,46.08 207.72,44.93 207.67,44.88
PWR_CHG_UGATE1 on BOTTOM: 202.54,50.67 202.54,51.61 202.11,52.05 201.91,52.05 201.65,52.3 201.65,52.6 201.83,52.78 202.14,52.78 202.39,52.53 202.39,52.2 202.75,51.84 202.75,50.7 202.72,50.67
PWR_CHG_UGATE2 on BOTTOM: 199.95,48.64 199.75,48.85 199.75,49.18 199.9,49.33 201.58,49.33 201.63,49.28 201.63,49.12 201.58,49.07 200.69,49.07 200.26,48.64
PWR_CHG_VBATIN on BOTTOM: 170.54,33.68 170.54,34.82 170.77,35.05 170.77,35.31 171.02,35.56 171.02,37.39 171.38,37.75 171.38,40.51 172.44,40.51 172.9,40.06 172.9,36.4 173.05,36.25 175.87,36.25 176.63,35.49 176.63,34.06 176.46,33.88 173.82,33.88 173.61,33.68
PWR_CHG_VBATIN_R on BOTTOM: 173.1,36.45 173.1,40.44 173.13,40.46 174.15,40.46 174.55,40.06 177.85,40.06 177.98,40.18 177.98,40.44 181.82,40.44 182.45,39.8 182.88,39.8 182.88,36.78 182.86,36.76 181.79,36.76 180.9,37.64 177.9,37.64 176.71,36.45
PWR_CHG_VBATIN_R on L5: 194.64,47.45 195.41,47.45 195.58,47.27 195.58,46.86 195.13,46.41 195.13,45.7 194.92,45.49 194.34,45.49 194.08,45.75 194.08,46.89
PWR_CHG_VDDP on BOTTOM: 200.97,50.32 199.6,51.69 198.76,51.69 198.4,52.05 198.4,53.29 198.61,53.49 199.04,53.49 199.34,53.19 199.34,52.83 200.18,52 200.18,51.79 200.66,51.31 200.82,51.31 201.58,50.55 201.58,50.37 201.53,50.32 ; 1 cut-out
PWR_DCBATOUT_1D05V on TOP: 105.87,134.67 105.44,135.1 105.44,137.44 105.51,137.52 108.03,137.52 108.21,137.34 108.21,135.05 107.83,134.67
PWR_DCBATOUT_1D05V on BOTTOM: 105.29,134.55 105.03,134.8 105.03,136.07 104.65,136.45 101.1,136.45 101.1,137.47 101.22,137.59 103.89,137.59 104.14,137.85 104.14,139.37 104.19,139.42 104.6,139.42 104.65,139.37 104.65,138.89 104.8,138.74 108.23,138.74 108.61,139.12 108.61,140.9 108.69,140.97 109.65,140.97 109.76,140.87 109.76,139.04 108.64,137.92 108.64,136.88 108.08,136.32 108.08,134.93 107.7,134.55 ; 1 cut-out
PWR_DCBATOUT_1D35V on TOP: 107.95,146.38 107.88,146.46 107.88,147.83 108.08,148.03 111.05,148.03 111.23,147.85 111.23,146.48 111.13,146.38
PWR_DCBATOUT_1D35V on BOTTOM: 108.11,145.85 107.95,146 107.95,147.5 109.6,149.15 110.75,149.15 110.87,149.02 110.87,147.75 111.12,147.51 111.12,147.49 111.37,147.23 111.37,146.75 111.51,146.61 111.89,146.61 112.02,146.48 112.02,146.03 111.84,145.85
PWR_DCBATOUT_VCCGTA on TOP: 79.89,138.71 79.12,139.47 78.79,139.47 78.46,139.8 78.46,142.19 78.74,142.47 82.65,142.47 83.32,143.13 84.97,143.13 85.63,142.47 89.11,142.47 89.31,142.27 89.31,140.31 87.71,138.71 ; 4 cut-outs
PWR_DCBATOUT_VCCGTA on BOTTOM: 83.7,135.82 83.57,135.94 83.57,136.96 83.82,137.21 84.97,137.21 85.09,137.34 85.09,138.1 85.5,138.51 85.91,138.51 86.11,138.71 86.11,142.34 86.54,142.77 87.99,142.77 89.16,143.94 90.35,143.94 92.81,146.41 96.17,146.41 96.45,146.13 96.45,144.1 96.42,144.07 94.44,144.07 94.26,143.89 94.26,140.74 94.11,140.59 93.17,140.59 93.09,140.67 93.09,141.33 92.94,141.48 90.22,141.48 90.15,141.4 90.15,140.77 87.63,138.25 87.63,135.94 87.51,135.82 ; 12 cut-outs
PWR_DCBATOUT_VCCGTA on BOTTOM: 77.35,135.79 77.27,135.87 77.27,136.93 77.37,137.03 78.69,137.03 78.82,137.16 78.82,138.58 78.39,139.02 78.39,142.47 78.57,142.65 79.86,142.65 80.52,141.99 80.52,138.48 80.19,138.15 80.19,136.3 79.68,135.79 ; 4 cut-outs
PWR_DCBATOUT_VCCGTA on L2GND: 83.78,138.67 83.39,139.05 82.35,139.05 82.09,138.8 79.71,138.8 78.68,139.83 78.68,142.21 78.82,142.36 88.32,142.36 89.22,141.45 89.22,140.47 87.43,138.67
PWR_DCBATOUT_VCCGTA on L6: 79.25,142.29 79.25,138.94 79.71,138.48 88.32,138.48 89.31,139.47 89.31,141.07 87.71,142.67 79.63,142.67
PWR_DCBATOUT_VCCSA on BOTTOM: 92.21,135.18 92.08,135.31 92.08,137.75 91.93,137.9 91.65,137.9 91.57,137.97 91.57,141.12 91.67,141.23 92.87,141.23 92.87,140.62 93.09,140.39 94.11,140.39 94.21,140.29 94.21,138.76 94.29,138.69 95.53,138.69 95.63,138.58 95.63,135.31 95.51,135.18 ; 1 cut-out
PWR_DCBATOUT_VCORE on TOP: 68.79,135.43 68.56,135.66 68.56,140.49 68.76,140.69 71.55,140.69 71.76,140.49 71.76,139.45 71.96,139.24 71.96,138.2 71.76,138 71.76,136.88 71.94,136.7 71.94,135.61 71.76,135.43 ; 13 cut-outs
PWR_DCBATOUT_VCORE on BOTTOM: 66.7,135.61 66.53,135.79 66.53,137.01 66.6,137.09 68.08,137.09 68.15,137.16 68.15,143.18 68.68,143.71 71.33,143.71 71.4,143.64 71.4,140.77 71.83,140.34 73.03,140.34 73.18,140.18 73.18,138.13 73.03,137.97 71.3,137.97 70.64,137.31 70.64,135.97 70.28,135.61 ; 2 cut-outs
PWR_DCBATOUT_VCORE on L2GND: 68.41,135.62 68.01,136.02 68.01,139.04 69.81,140.83 70.79,140.83 71.06,140.56 71.06,135.77 70.92,135.62
PWR_DCBATOUT_VCORE on L6: 68.08,138.79 68.08,135.94 68.33,135.69 70.18,135.69 71.33,136.83 71.33,140.41 71.07,140.67 69.95,140.67
PWR_DCBATOUT_VDDQ on TOP: 115.71,30.49 115.19,31.01 115.19,33.12 116.39,34.32 119.31,34.32 119.66,33.96 122.2,33.96 122.35,33.81 122.35,32.44 121.47,31.55 120.78,31.55 120.37,31.14 118.65,31.14 118.63,31.15 118.07,31.15 117.53,30.61 116.94,30.61 116.83,30.49 ; 1 cut-out
PWR_DCBATOUT_VDDQ on BOTTOM: 116,29.92 115.95,29.97 115.95,31.57 115.8,31.73 115.8,32.39 116.06,32.64 118.32,32.64 119.31,33.63 119.31,35.13 119.89,35.71 121.19,35.71 121.72,36.25 122.86,36.25 123.12,35.99 123.12,33.55 121.19,31.62 118.72,31.62 118.67,31.68 117.27,31.68 117.17,31.57 117.17,30 117.1,29.92
PWR_VCCGT_SWA on BOTTOM: 81.84,129.34 81.44,129.74 81.44,131.73 80.83,132.34 80.83,134.72 80.9,134.8 81.41,134.8 81.54,134.67 81.54,133.53 81.79,133.28 85.4,133.28 85.78,132.89 85.78,129.41 85.7,129.34
PWR_VCCGT_SWB on BOTTOM: 76.41,129.26 76.23,129.44 75.06,129.44 74.4,130.1 74.4,134.52 74.53,134.65 75.24,134.65 75.31,134.57 75.31,133.35 75.47,133.2 79.12,133.2 79.23,133.1 79.23,129.97 78.69,129.44 77.47,129.44 77.3,129.26
PWR_VCCGT_VCCDB on TOP: 75.31,136.53 75.29,136.55 75.29,136.98 75.06,137.21 75.06,137.85 75.24,138.02 75.95,138.02 76.1,138.18 76.1,138.53 76.15,138.58 76.61,138.58 76.74,138.46 76.74,137.92 76.46,137.64 76.46,137.19 76.33,137.06 76.05,137.06 76.04,137.07 75.89,137.07 75.72,136.91 75.72,136.6 75.64,136.53 ; 1 cut-out
PWR_VCCSA_DRVH on BOTTOM: 96.04,133.91 95.89,134.06 95.89,134.7 96.24,135.05 96.98,135.05 97.01,135.03 97.01,134.24 96.68,133.91
PWR_VCCSA_DRVL on BOTTOM: 98.35,136.25 98.35,136.93 98.89,137.47 99.37,137.47 99.47,137.36 99.47,136.96 98.96,136.45 98.96,136.32 98.89,136.25
PWR_VCCSA_SW on BOTTOM: 98.12,133.91 97.92,134.11 97.92,134.27 98.35,134.7 98.35,135.05 98.38,135.08 98.94,135.08 98.99,135.03 98.99,134.24 98.66,133.91
PWR_VCCSA_SW on BOTTOM: 89.74,131.12 89.74,132.72 88.8,133.66 88.57,133.66 88.17,134.06 88.17,136.53 88.22,136.58 91.44,136.58 91.57,136.45 91.57,134.11 91.77,133.91 93.2,133.91 93.25,133.96 93.25,134.67 93.37,134.8 95,134.8 95.25,134.55 95.25,131.5 94.87,131.12
PWR_VCORE_BOOT on TOP: 65.99,137.06 65.97,137.09 65.97,137.77 66.42,138.23 66.42,138.58 66.53,138.69 67.36,138.69 67.47,138.58 67.47,138.3 66.96,137.8 66.96,137.14 66.88,137.06
PWR_VCORE_SW on BOTTOM: 65.38,129.21 64.63,129.96 64.63,131.56 63.83,132.36 63.83,134.62 63.88,134.67 64.52,134.67 64.65,134.55 64.65,133.28 64.77,133.15 68.46,133.15 69.35,132.26 69.35,129.34 69.22,129.21
PWR_VCORE_VCC_R on BOTTOM: 66.35,138.53 66.27,138.61 66.27,139.68 66.32,139.73 66.83,139.73 67.06,139.96 67.06,140.08 67.11,140.13 67.62,140.13 67.69,140.06 67.69,138.91 67.47,138.69 67.11,138.69 66.96,138.53 ; 1 cut-out
PWR_VDDQ on TOP: 113.62,38.58 113.24,38.96 113.24,40.51 114.81,42.09 119.61,42.09 119.87,41.84 119.87,38.86 119.59,38.58
PWR_VDDQ on BOTTOM: 111.97,38 111.51,38.46 111.51,41.15 111.94,41.58 119.97,41.58 120.65,40.9 120.65,38.66 119.99,38 ; 6 cut-outs
PWR_VDDQ_PH on TOP: 114.68,34.22 114.3,34.6 114.3,35.99 114.56,36.25 116.08,36.25 116.34,35.99 116.34,34.6 115.95,34.22
PWR_VDDQ_PH on BOTTOM: 114.25,28.5 114.18,28.58 114.18,32.23 114.1,32.31 114.1,35.31 114.91,36.12 116.92,36.12 117.68,35.36 117.68,32.82 117.61,32.74 115.93,32.74 115.67,32.49 115.67,31.6 115.83,31.45 115.83,28.58 115.75,28.5
PWR_VDDQ_VCC on TOP: 112.5,28.65 112.35,28.8 111.56,28.8 111.46,28.91 111.46,29.36 111.74,29.64 111.74,30.15 111.81,30.23 113.11,30.23 113.19,30.15 113.19,29.08 112.75,28.65 ; 1 cut-out
PWR_VDDQ_VLDOIN on TOP: 122.05,37.77 121.85,37.97 121.85,38.2 122.05,38.41 122.99,38.41 123.27,38.69 123.27,39.04 120.73,41.58 120.73,42.11 120.78,42.17 122.38,42.17 122.58,41.96 122.58,40.77 124.01,39.35 124.01,38.2 123.57,37.77
PWR_VGA_NVVDD_BOOT1 on BOTTOM: 146.31,80.65 146.31,80.85 146.82,81.36 147.17,81.36 147.27,81.46 147.27,81.71 147.32,81.76 148.01,81.76 148.03,81.74 148.03,80.9 147.98,80.85 147.3,80.85 147.09,80.65
PWR_VGA_NVVDD_BOOT2 on BOTTOM: 143.13,80.67 142.9,80.9 141.79,80.9 141.74,80.95 141.74,81.64 141.79,81.69 143.39,81.69 144.12,80.95 144.12,80.72 144.07,80.67
PWR_VGA_NVVDD_HG1 on BOTTOM: 147.4,80.01 147.17,80.24 146.31,80.24 146.31,80.44 147.22,80.44 147.45,80.67 147.86,80.67 147.96,80.57 147.96,80.19 147.78,80.01
PWR_VGA_NVVDD_HG2 on BOTTOM: 142.12,79.99 141.99,80.11 141.99,80.44 142.32,80.77 142.85,80.77 143.16,80.47 144.07,80.47 144.15,80.39 144.15,80.29 144.07,80.21 142.78,80.21 142.55,79.99
PWR_VGA_NVVDD_LGATE1 on BOTTOM: 145.55,81.05 145.52,81.08 145.52,81.97 145.6,82.04 145.6,82.4 145.88,82.68 146.15,82.68 146.28,82.55 146.28,82.25 145.72,81.69 145.72,81.08 145.7,81.05
PWR_VGA_NVVDD_LGATE2 on BOTTOM: 144.76,81.05 144.71,81.1 144.71,81.84 144.25,82.3 144.25,82.96 144.58,83.29 144.88,83.29 145.01,83.16 145.01,82.73 144.78,82.5 144.78,82.14 144.91,82.02 144.91,81.1 144.86,81.05
PWR_VGA_NVVDD_PHASE1 on TOP: 151.01,83.49 150.88,83.62 150.88,88.83 150.5,89.21 149.27,89.21 149.04,89.43 149.04,92.77 149.2,92.94 153.27,92.94 153.67,92.53 153.67,89.33 154.05,88.95 154.05,83.62 153.93,83.49
PWR_VGA_NVVDD_PHASE1 on BOTTOM: 145.95,81.05 145.93,81.08 145.93,81.69 145.95,81.71 146.31,81.71 146.71,82.12 146.92,82.12 147.09,81.94 147.09,81.79 146.36,81.05
PWR_VGA_NVVDD_PHASE1 on BOTTOM: 150.88,83.49 150.75,83.62 150.75,88.83 150.37,89.21 149.1,89.21 148.97,89.33 148.97,92.71 149.2,92.94 153.39,92.94 154.38,91.95 154.38,90.27 155.04,89.61 155.04,89.26 154.87,89.08 154.16,89.08 153.93,88.85 153.93,83.62 153.8,83.49
PWR_VGA_NVVDD_PHASE2 on TOP: 141.61,83.49 141.48,83.62 141.48,88.95 141.23,89.21 140.97,89.21 140.85,89.33 140.85,92.81 141.07,93.04 145.11,93.04 145.29,92.86 145.29,92.48 144.66,91.85 144.66,83.62 144.53,83.49
PWR_VGA_NVVDD_PHASE2 on BOTTOM: 144.28,81.05 143.59,81.74 143.59,82.37 143.36,82.6 142.98,82.6 142.93,82.65 142.93,83.26 142.98,83.31 143.46,83.31 144.12,82.65 144.12,82.27 144.5,81.89 144.5,81.08 144.48,81.05
PWR_VGA_NVVDD_PHASE2 on BOTTOM: 141.61,83.49 141.48,83.62 141.48,88.95 141.35,89.08 141.1,89.08 140.85,89.33 140.85,92.81 141.07,93.04 145.27,93.04 145.55,92.76 145.55,89.71 145.42,89.59 145.42,89.21 145.16,88.95 144.78,88.95 144.53,88.7 144.53,83.75 144.28,83.49
PWR_VGA_SNUB1 on TOP: 147.2,90.25 147.12,90.32 147.12,92.3 147.32,92.51 148.72,92.51 148.86,92.37 148.86,91.89 148.9,91.85 148.9,90.32 148.82,90.25 ; 1 cut-out
PWR_VGA_SNUB2 on TOP: 145.14,90.12 145.01,90.25 145.01,91.64 145.19,91.82 146.71,91.82 146.89,91.64 146.89,90.43 146.79,90.32 146.26,90.32 146.05,90.12 ; 1 cut-out
REGOUT on TOP: 47.73,84.84 47.73,85.29 48.47,86.03 49.28,86.03 49.48,85.83 49.48,85.52 49.36,85.4 48.97,85.4 48.42,84.84
REGOUT on BOTTOM: 48.34,85.22 48.24,85.32 48.24,85.9 48.03,86.11 48.03,86.49 48.16,86.62 48.75,86.62 48.9,86.46 48.9,86.41 49.28,86.03 49.91,86.03 50.04,85.9 50.04,85.65 49.79,85.4 49.36,85.4 49.18,85.22 ; 1 cut-out
RING2_HPMIC1 on TOP: 16.51,8.18 16.39,8.31 16.39,9.83 16.51,9.96 17.15,9.96 17.28,9.83 17.28,8.31 17.15,8.18
TP_VDD on TOP: 104.22,27.87 103.97,28.12 97.92,28.12 97.89,28.14 95.46,28.14 95.25,28.35 95.25,28.88 95.38,29.01 99.32,29.01 99.72,29.41 99.72,31.42 103.05,34.75 103.28,34.75 103.51,34.52 103.51,32.89 101.6,30.99 101.6,29.39 101.98,29.01 106.18,29.01 106.68,29.52 107.72,29.52 107.86,29.38 107.86,28.67 107.06,27.87 ; 4 cut-outs
TP_VDD on BOTTOM: 95.38,28.32 95.2,28.5 95.2,29.16 94.95,29.41 93.96,29.41 93.75,29.62 93.75,30.15 93.91,30.3 94.85,30.3 95.08,30.53 95.08,31.42 95.18,31.52 95.86,31.52 95.96,31.42 95.96,28.65 95.63,28.32
USB30_PS_VCC on TOP: 13.21,37.75 11.28,39.68 10.16,39.68 9.4,40.44 9.4,46.41 9.91,46.92 11.05,46.92 11.79,47.65 17.68,47.65 17.69,47.64 18.43,47.64 18.8,47.27 18.8,46.53 19.18,46.15 20.12,46.15 20.3,46.33 20.3,48.52 21.36,49.58 21.36,50.57 21.39,50.6 22.33,50.6 22.81,50.12 22.81,48.49 22.05,47.73 22.05,45.21 21.21,44.38 18.29,44.38 18.04,44.63 17.4,44.63 16.51,45.52 12.65,45.52 12.25,45.11 12.25,42.62 12.65,42.22 12.65,40.84 13.02,40.48 14.06,40.48 15.45,39.09 17.81,39.09 17.88,39.02 17.88,37.85 17.78,37.75 ; 2 cut-outs
USB30_PS_VCC on BOTTOM: 21.62,55.47 21.16,55.93 21.16,56.21 20.81,56.57 18.88,56.57 18.46,56.99 15.71,56.99 14.25,58.45 12.93,58.45 12.55,58.83 12.55,60.61 12.75,60.81 15.9,60.81 17.17,59.54 18.95,59.54 20.83,57.66 20.83,57.63 22.1,56.36 22.1,55.68 21.9,55.47 ; 5 cut-outs
USB30_PS_VCC on L3: 15.88,49.58 15.5,49.2 15.5,46.79 13.85,45.14 12.68,45.14 12.3,44.76 9.5,44.76 9.17,45.09 9.17,46.31 9.78,46.92 11.18,46.92 12.2,47.93 12.7,47.93 13.59,48.82 13.59,51.11 13.85,51.36 13.85,57.2 12.32,58.73 12.32,60.38 13.21,61.27 15.24,61.27 15.88,60.63
USB_ADT on TOP: 36.17,121.57 36.1,121.64 36.1,122.18 35.94,122.33 35.94,125.91 36.07,126.04 38.48,126.04 38.74,125.78 38.74,124 38.99,123.75 39.35,123.75 39.45,123.65 39.45,121.97 39.04,121.57 ; 1 cut-out
VCP_VBUS on TOP: 42.57,123.37 42.47,123.47 42.47,123.78 42.37,123.88 42.07,123.88 41.96,123.98 41.96,124.44 41.79,124.61 41.79,126.42 43.34,126.42 43.44,126.32 43.44,124.64 43.31,124.51 43.06,124.51 42.85,124.31 42.85,123.45 42.78,123.37
VID_PLLVDD_L on TOP: 131.93,124.59 130.61,125.91 130.18,125.91 130.05,126.04 130.05,126.47 129.42,127.1 129.42,128.3 129.75,128.63 129.9,128.63 130.46,128.07 130.69,128.07 132.21,126.54 132.21,125.86 132.69,125.38 132.69,125.07 132.21,124.59 ; 5 cut-outs
VREG3PD on TOP: 52.33,127.56 52.1,127.79 51.39,127.79 51.13,128.04 51.13,128.47 51.21,128.55 51.77,128.55 51.9,128.68 51.9,128.8 52,128.91 52.63,128.91 52.89,129.16 53.47,129.16 53.72,128.91 53.72,127.89 53.62,127.79 52.86,127.79 52.63,127.56 ; 3 cut-outs

Small or netless copper shapes (teardrops, artwork), in the pictures only: 59 on L2GND, 59 on L3, 59 on L4VCC, 59 on L5, 59 on L6, 59 on L7GND, 3 on TOP, 4 on BOTTOM

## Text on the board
Ref Des/Silkscreen Bottom: 15 | 14L | Narrow | 14L/Bolt15 | 14L/15L | 15L/2SP/BT | 2SP/15 | F6501:1.1A/6V | X1801:24MHZ | F5504:1.1A/6V | F5503:1.1A/24V | X7901:27MHZ | MADE IN TAIWAN | Y3TF7 | Bolt 2SP DIS 4GB | 17931-1
User.Comments: CR_2_2 | SIR_MAKOY_1107
Ref Des/Silkscreen Top: F5701:1.1A/6V | X3101:25MHZ | X1802:32.768KHZ | X2401:32.768KHZ | F5506:1.1A/6V | F5505:1.1A/6V
User.27: ByImpedance:100.0_DP@_REF_L1=("4.0/10.0(L2)" "3.5/7.0(L2)")|_REF_L6=("4.0/11.0(L4/L7)" "3.5/7.0(L4/L7)")|Type="DP"|imp="100.0"|_REF_L5=("4.0/11.0(L4/L7)" "3.5/7.0(L4/L7)")|_REF_L8=("4.0/10.0(L7)" "3.5/7.0(L7)") | ByImpedance:20.0_SE@_REF_L1=("21.0(L2)")|_REF_L6=("21.0(L4/L7)" "16.5(L5/L7)")|Type="SE"|_REF_L3=("16.5(L2/L4)")|imp="20.0"|_REF_L5=("21.0(L4/L7)")|_REF_L8=("21.0(L7)") | ByImpedance:33.0_SE@_REF_L1=("10.0(L2)")|_REF_L6=("10.0(L4/L7)" "8.0(L5/L7)")|Type="SE"|_REF_L3=("8.0(L2/L4)")|imp="33.0"|_REF_L5=("10.0(L4/L7)")|_REF_L8=("10.0(L7)") | ByImpedance:37.5_SE@_REF_L1=("8.0(L2)")|_REF_L6=("8.0(L4/L7)" "6.5(L5/L7)")|Type="SE"|_REF_L3=("6.5(L2/L4)")|imp="37.5"|_REF_L5=("8.0(L4/L7)")|_REF_L8=("8.0(L7)") | ByImpedance:39.0_SE@_REF_L1=("7.5(L2)")|_REF_L6=("6.0(L5/L7)" "7.5(L4/L7)")|Type="SE"|_REF_L3=("6.0(L2/L4)")|imp="39.0"|_REF_L5=("7.5(L4/L7)")|_REF_L8=("7.5(L7)") | ByImpedance:40.0_SE@_REF_L1=("7.0(L2)")|_REF_L6=("5.5(L5/L7)" "7.0(L4/L7)")|Type="SE"|_REF_L3=("5.5(L2/L4)")|imp="40.0"|_REF_L5=("7.0(L4/L7)")|_REF_L8=("7.0(L7)") | ByImpedance:45.0_SE@_REF_L1=("5.5(L2)")|_REF_L6=("5.5(L4/L7)" "4.5(L5/L7)")|Type="SE"|_REF_L3=("4.5(L2/L4)")|imp="45.0"|_REF_L5=("5.5(L4/L7)")|_REF_L8=("5.5(L7)") | ByImpedance:48.0_SE@_REF_L1=("5.0(L2)")|_REF_L6=("5.0(L4/L7)" "4.0(L5/L7)")|Type="SE"|_REF_L3=("4.0(L2/L4)")|imp="48.0"|_REF_L5=("5.0(L4/L7)")|_REF_L8=("5.0(L7)") | ByImpedance:50.0_SE@_REF_L1=("10.0/4.5/10.0(L1/L2)" "4.5(L2)")|_REF_L6=("4.5(L4/L7)" "3.5(L5/L7)")|Type="SE"|_REF_L3=("3.5(L2/L4)")|imp="50.0"|_REF_L5=("4.5(L4/L7)")|_REF_L8=("10.0/4.5/10.0(L7/L8)" "4.5(L7)") | ByImpedance:55.0_SE@_REF_L1=("3.5(L2)")|_REF_L6=("3.5(L4/L7)")|Type="SE"|imp="55.0"|_REF_L5=("3.5(L4/L7)")|_REF_L8=("3.5(L7)") | ByImpedance:60.0_DP@_REF_L1=("9.0/4.0(L2)")|_REF_L6=("8.0/4.0(L5/L7)" "9.0/4.0(L4/L7)")|Type="DP"|_REF_L3=("8.0/4.0(L2/L4)")|imp="60.0"|_REF_L5=("9.0/4.0(L4/L7)")|_REF_L8=("9.0/4.0(L7)") | ByImpedance:63.0_DP@_REF_L1=("9.0/5.0(L2)")|_REF_L6=("8.5/4.0(L4/L7)" "7.0/4.0(L5/L7)")|Type="DP"|_REF_L3=("7.0/4.0(L2/L4)")|imp="63.0"|_REF_L5=("8.5/4.0(L4/L7)")|_REF_L8=("9.0/5.0(L7)") | ByImpedance:68.0_DP@_REF_L1=("8.0/5.5(L2)")|_REF_L6=("6.0/4.0(L5/L7)" "7.5/5.0(L4/L7)")|Type="DP"|_REF_L3=("6.0/4.0(L2/L4)")|imp="68.0"|_REF_L5=("7.5/5.0(L4/L7)")|_REF_L8=("8.0/5.5(L7)") | ByImpedance:70.0_DP@_REF_L1=("7.5/5.5(L2)")|_REF_L6=("6.0/5.0(L5/L7)" "7.0/4.5(L4/L7)")|Type="DP"|_REF_L3=("6.0/5.0(L2/L4)")|imp="70.0"|_REF_L5=("7.0/4.5(L4/L7)")|_REF_L8=("7.5/5.5(L7)") | ByImpedance:72.0_DP@_REF_L1=("6.5/4.5(L2)")|_REF_L6=("5.5/4.0(L5/L7)" "6.0/4.0(L4/L7)")|Type="DP"|_REF_L3=("5.5/4.0(L2/L4)")|imp="72.0"|_REF_L5=("6.0/4.0(L4/L7)")|_REF_L8=("6.5/4.5(L7)") | ByImpedance:75.0_DP@_REF_L1=("6.5/5.5(L2)")|_REF_L6=("6.0/4.5(L4/L7)" "5.0/4.0(L5/L7)")|Type="DP"|_REF_L3=("5.0/4.0(L2/L4)")|imp="75.0"|_REF_L5=("6.0/4.5(L4/L7)")|_REF_L8=("6.5/5.5(L7)") | ByImpedance:80.0_DP@_REF_L1=("6.0/6.0(L2)" "5.5/5.0(L2)")|_REF_L6=("5.0/4.5(L4/L7)" "4.0/4.0(L5/L7)")|Type="DP"|_REF_L3=("4.0/4.0(L2/L4)")|imp="80.0"|_REF_L5=("5.0/4.5(L4/L7)")|_REF_L8=("5.5/5.0(L7)" "6.0/6.0(L7)") | ByImpedance:83.0_DP@_REF_L1=("4.5/4.0(L2)")|_REF_L6=("4.0/4.5(L5/L7)" "4.5/4.5(L4/L7)")|Type="DP"|_REF_L3=("4.0/4.5(L2/L4)")|imp="83.0"|_REF_L5=("4.5/4.5(L4/L7)")|_REF_L8=("4.5/4.0(L7)") | ByImpedance:85.0_DP@_REF_L1=("4.0/4.0(L2)" "4.5/4.5(L2)" "5.0/6.0(L2)")|_REF_L6=("4.0/4.0(L4/L7)" "3.5/4.0(L5/L7)" "4.5/5.0(L4/L7)" "4.0/5.0(L5/L7)")|Type="DP"|_REF_L3=("3.5/4.0(L2/L4)" "4.0/5.0(L2/L4)")|imp="85.0"|_REF_L5=("4.0/4.0(L4/L7)" "4.5/5.0(L4/L7)")|_REF_L8=("4.5/4.5(L7)" "4.0/4.0(L7)" "5.0/6.0(L7)") | ByImpedance:88.0_DP@_REF_L1=("4.0/4.5(L2)")|_REF_L6=("3.5/4.0(L4/L7)" "4.0/5.0(L4/L7)")|Type="DP"|_REF_L3=("4.0/6.5(L2/L4)" "3.5/4.5(L2/L4)")|imp="88.0"|_REF_L5=("3.5/4.0(L4/L7)" "4.0/5.0(L4/L7)")|_REF_L8=("4.0/4.5(L7)") | ByImpedance:90.0_DP@_REF_L1=("4.0/5.0(L2)")|_REF_L6=("4.0/8.0(L5/L7)" "3.5/5.0(L5/L7)" "4.0/5.5(L4/L7)" "3.5/4.5(L4/L7)")|Type="DP"|_REF_L3=("4.0/8.0(L2/L4)" "3.5/5.0(L2/L4)")|imp="90.0"|_REF_L5=("4.0/5.5(L4/L7)" "3.5/4.5(L4/L7)")|_REF_L8=("4.0/5.0(L7)") | LayerIndex:nil | Source:8-1.0-12g.xls | artWorks:("_REF_L5" "_REF_L3" "_REF_L6" "_REF_L8" "_REF_L1") | gtImpOutlineUsed:BOARD GEOMETRY/PANEL_OUTLINE
